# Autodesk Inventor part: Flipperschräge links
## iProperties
Created: 2017-04
Part Number: Flipperschräge links
Material: Standard
Document SubType Name: Blech
Designer: Acer
Density: 1 g/cm^3
Sheet Metal Rule: Standard_mm
Author: Acer
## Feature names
1. Extrusion1
2. Rundung1 [Fillet]
3. Rundung2 [Fillet]
